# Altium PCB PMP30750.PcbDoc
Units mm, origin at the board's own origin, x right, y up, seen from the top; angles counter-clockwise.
Board outline 55.88 x 60.07 mm, 2 copper layers (Top Layer, Bottom Layer), stack 1.575 mm thick; 36 components, 18 nets, 83 pads, 28 vias.
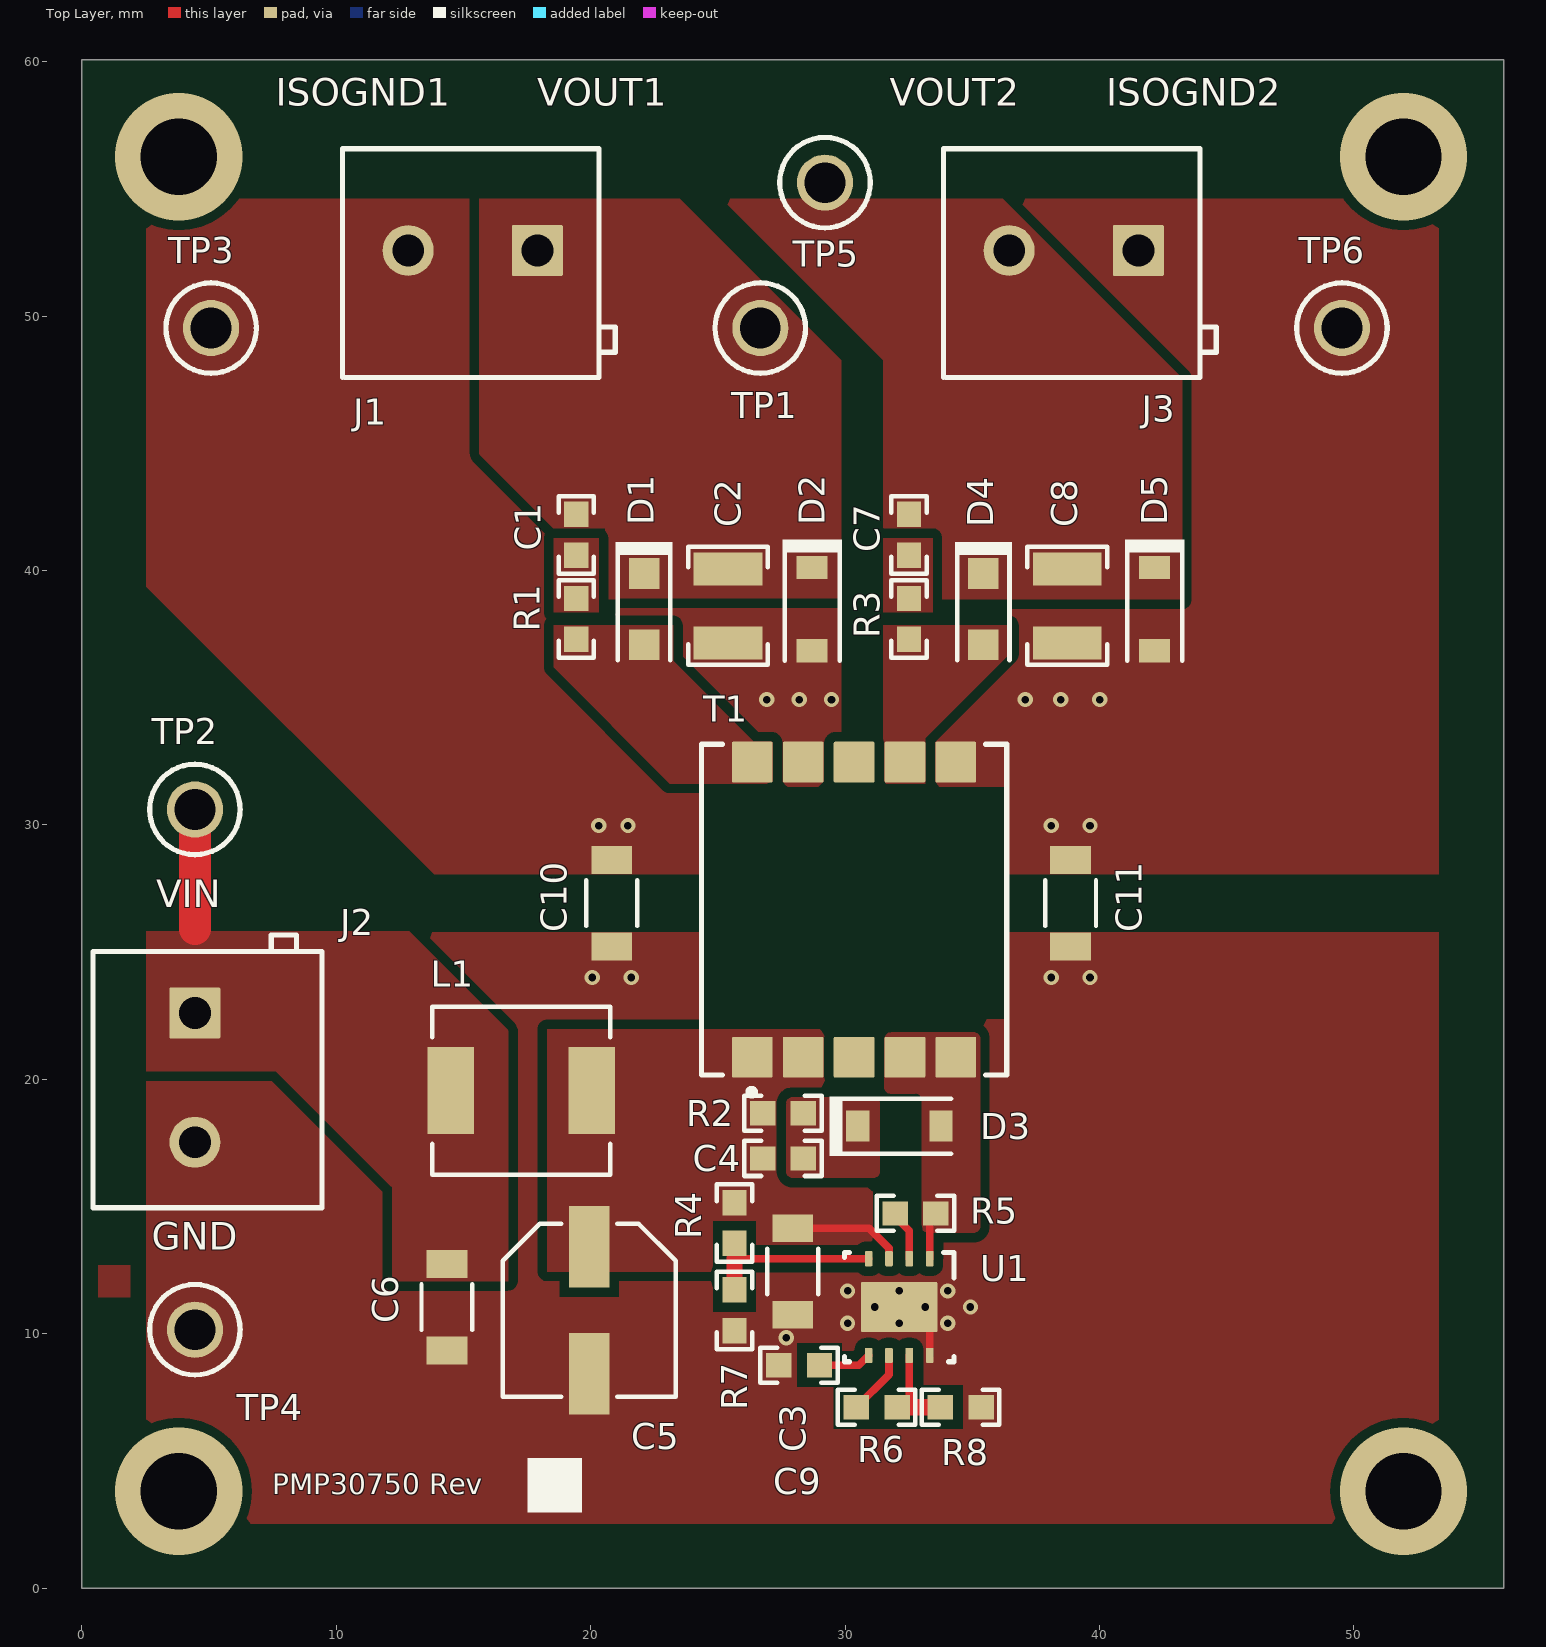
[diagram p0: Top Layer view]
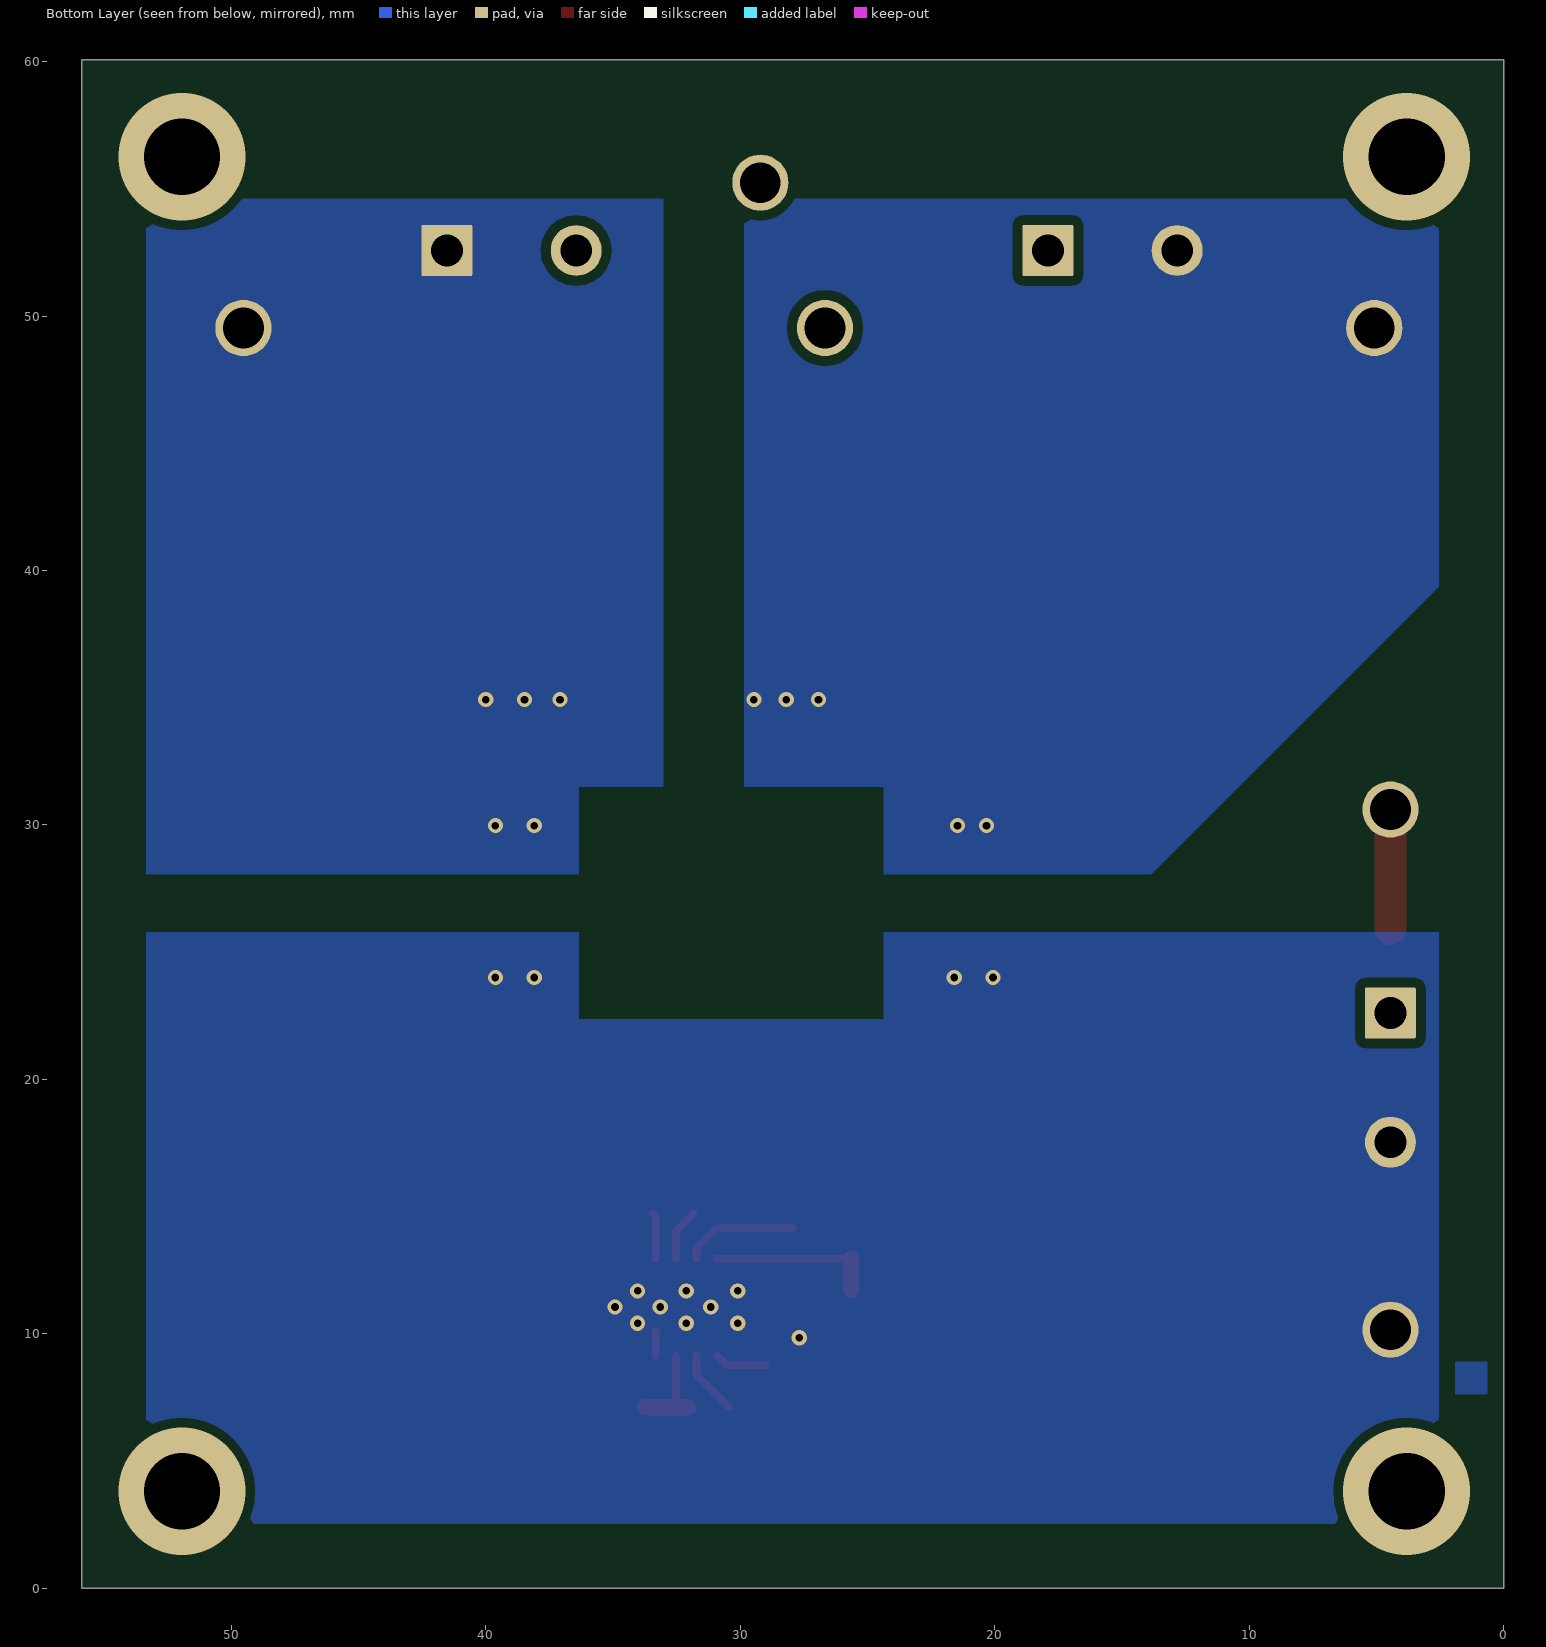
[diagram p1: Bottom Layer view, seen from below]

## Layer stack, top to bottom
Top Solder: solder mask 0.0102, Solder Resist, Dk 3.5
Top Layer: signal copper 0.0356
Dielectric1: core 1.5037, FR-4, Dk 4.8
Bottom Layer: signal copper 0.0356
Bottom Solder: solder mask 0.0102, Solder Resist, Dk 3.5

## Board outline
0,0 55.88,0 55.88,60.071 0,60.071

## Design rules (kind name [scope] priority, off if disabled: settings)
AcuteAngle [All] p1: minimum=4.50000000000000E+0001 checktracksonly=FALSE
AssemblyTestPointUsage [All] p1: valid=2
Clearance Clearance_Keepouts [((IsTrack Or IsArc) And Not InPoly) And IsFree and IsKeepOut vs ((IsTrack Or IsArc) And Not InPoly) And IsFree and IsKeepOut] p1: gap=0 ignorepadtopadclearanceinfootprint=FALSE
Clearance Clearance_BoardEdge_MountingHoles [OnCopper and InComponentClass('Mounting Holes') vs IsKeepOut] p2: gap=1.016 ignorepadtopadclearanceinfootprint=FALSE except(0: Arc-Hole Track-Hole SMDPad-Hole THPad-Hole Via-Hole Fill-Hole Poly-Hole Region-Hole Text-Hole)
Clearance Clearance_BoardEdge_Poly [OnCopper and InPoly vs IsKeepOut] p3: gap=0.635 ignorepadtopadclearanceinfootprint=FALSE except(0: Arc-Hole Track-Hole SMDPad-Hole THPad-Hole Via-Hole Fill-Hole Poly-Hole Region-Hole Text-Hole)
Clearance Clearance_BoardEdge [OnCopper and Not InComponentClass('Logo') and not InComponentClass('FiducialMark') and not InRegion(1000,500,4000,800) and Not IsKeepout vs IsKeepOut] p4: gap=1.905 ignorepadtopadclearanceinfootprint=FALSE except(0: Arc-Hole Track-Hole SMDPad-Hole THPad-Hole Via-Hole Fill-Hole Poly-Hole Region-Hole Text-Hole)
Clearance Clearance_Poly [InPolygon] p5: gap=0.381 ignorepadtopadclearanceinfootprint=FALSE except(0: Arc-Hole Track-Hole SMDPad-Hole THPad-Hole Via-Hole Fill-Hole Poly-Hole Region-Hole Text-Hole)
Clearance [All] p6: gap=0.2 ignorepadtopadclearanceinfootprint=FALSE except(0: Arc-Hole Track-Hole SMDPad-Hole THPad-Hole Via-Hole Fill-Hole Poly-Hole Region-Hole Text-Hole)
ComponentClearance ComponentClearance_MountingHoles_FiducialMarks [InComponentClass('Mounting Holes') vs InComponentClass('FiducialMark')] p1: gap=1.27 collisioncheckmode=3 verticalgap=0.254 showdistances=FALSE
ComponentClearance ComponentClearance_Shunt [InComponentClass('Header') vs InComponentClass('Shunt')] p2: gap=0 collisioncheckmode=3 verticalgap=0 showdistances=FALSE
ComponentClearance ComponentClearance_Logo [InComponentClass('Logo')] p3: gap=1.27 collisioncheckmode=3 verticalgap=0.254 showdistances=FALSE
ComponentClearance ComponentClearance_ScrewToNut [(HasFootprint('NY PMS 440 0025 PH')) vs (HasFootprint('Keystone_1902C'))] p4: gap=0.127 collisioncheckmode=3 verticalgap=0.254 showdistances=FALSE
ComponentClearance ComponentClearance_MountingHoles [InComponentClass('Mounting Holes')] p5: gap=6.35 collisioncheckmode=3 verticalgap=2540 showdistances=FALSE
ComponentClearance ComponentClearance_SmallPassives [HasFootprint('0201*') or HasFootprint('0402*') or HasFootprint('0508') or HasFootprint('0603*') or HasFootprint('0612') or HasFootprint('0805*') or HasFootprint('0815*') or HasFootprint('0830*') or HasFootprint('1206*') or HasFootprint('1210*') or HasFootprint('1808*') or HasFootprint('1812*') or HasFootprint('1825*') or HasFootprint('2010*') or HasFootprint('2220*') or HasFootprint('2225*') or HasFootprint('2512*') or HasFootprint('2728*') or HasFootprint('3518*') vs HasFootprint('0201*') or HasFootprint('0402*') or HasFootprint('0508') or HasFootprint('0603*') or HasFootprint('0612') or HasFootprint('0805*') or HasFootprint('0815*') or HasFootprint('0830*') or HasFootprint('1206*') or HasFootprint('1210*') or HasFootprint('1808*') or HasFootprint('1812*') or HasFootprint('1825*') or HasFootprint('2010*') or HasFootprint('2220*') or HasFootprint('2225*') or HasFootprint('2512*') or HasFootprint('2728*') or HasFootprint('3518*')] p6: gap=0.508 collisioncheckmode=3 verticalgap=0.254 showdistances=FALSE
ComponentClearance ComponentClearance_THtoSMT [IsThruComponent vs IsSMTComponent] p7: gap=2.54 collisioncheckmode=3 verticalgap=0.762 showdistances=FALSE
ComponentClearance ComponentClearance_THtoTH [IsThruComponent vs IsThruComponent] p8: gap=3 collisioncheckmode=3 verticalgap=0.762 showdistances=FALSE
ComponentClearance [All] p9: gap=1.016 collisioncheckmode=3 verticalgap=0.254 showdistances=FALSE
DiffPairsRouting [All] p1: maxlimit=2.54 minlimit=0.254 mostfreqgap=0.254 toplayer_minwidth=0.381 toplayer_maxwidth=0.381 toplayer_prefwidth=0.381 bottomlayer_minwidth=0.381 bottomlayer_maxwidth=0.381 bottomlayer_prefwidth=0.381 maxuncoupledlength=25.4
FabricationTestPointUsage TestPointUsage [All] p1: valid=2 allowmultiple=FALSE
FabricationTestpoint Testpoint [All] p1: side=3 testpointundercomponent=TRUE minsize=1.016 maxsize=2.54 preferedsize=1.524 minholesize=0 maxholesize=1.016 preferedholesize=0.813 testpointgrid=0.025 allowsidetop=TRUE allowsidebottom=TRUE usegrid=TRUE gridtolerance=0
FanoutControl Fanout_LCC [IsLCC] p1: bgadir=Out bgaviamode=Centered fanoutstyle=Auto fanoutdirection=Alternating viagrid=0.025 // Fanout_LCC (Default Rule)
FanoutControl Fanout_BGA [IsBGA] p2: bgadir=Out bgaviamode=Centered fanoutstyle=Auto fanoutdirection=Alternating viagrid=0.025 // Fanout_BGA (Default Rule)
FanoutControl Fanout_Default [All] p4: bgadir=Out bgaviamode=Centered fanoutstyle=Auto fanoutdirection=Alternating viagrid=0.025 // Fanout_Default (Default Rule)
FanoutControl Fanout_Small [(CompPinCount < 5)] p5: bgadir=Out bgaviamode=Centered fanoutstyle=Auto fanoutdirection=OutThenIn viagrid=0.025 // Fanout_Small (Default Rule)
HoleSize [All] p1: absolutevalues=TRUE maxlimit=6.375 minlimit=0.3 maxpercent=80.000 minpercent=20.000
MinimumAnnularRing MinimumAnnularRing_ThermalPadVias [IsVia and InAnyComponent] p1: minimumring=0.15
MinimumAnnularRing [All] p2: minimumring=0.15
MinimumSolderMaskSliver MinimumSolderMaskSliver_Logo [InComponentClass('Logo') vs InComponentClass('Logo')] p1: minsoldermaskwidth=0.018
MinimumSolderMaskSliver [All] p2: minsoldermaskwidth=0.1
PlaneConnect [All] p1: planeconnectstyle=Relief reliefexpansion=0.254 reliefentries=4 reliefconductorwidth=0.254 reliefairgap=0.254
PolygonConnect [All] p1: connectstyle=Direct reliefconductorwidth=0.254 reliefentries=4 polygonreliefangle="90 Angle" airgapwidth=0.254
RoutingVias ThermalPadVias [IsVia and InAnyComponent] p1: holewidth=0.2 width=0.5 viastyle="Through Hole" minholewidth=0.3 minwidth=0.6 maxholewidth=0.33 maxwidth=0.6
RoutingVias [All] p2: holewidth=0.3 width=0.6 viastyle="Through Hole" minholewidth=0.3 minwidth=0.6 maxholewidth=1.016 maxwidth=1.651
SilkToBoardRegionClearance [Not ((IsComment or IsDesignator) And (Hide <> 'False')) and not InRegion(1000,500,4000,800)] p1:
SilkToSilkClearance SilkToSilkClearance_Pb-FreeLogo [(HasFootprint('Pb-Free_Overlay_Medium') OR HasFootprint('Pb-Free_Overlay_Small')) vs (HasFootprint('Pb-Free_Overlay_Medium') OR HasFootprint('Pb-Free_Overlay_Small'))] p1: silktosilkclearance=0
SilkToSilkClearance [All] p2: silktosilkclearance=0.102
SilkToSolderMaskClearance SilkToComonentPadClearance [IsPad and InAnycomponent] p1: minsilkscreentomaskgap=0.127 clearancetoexposedcopper=TRUE
SilkToSolderMaskClearance "Silk to Solder Mask Opening" [All] p2: minsilkscreentomaskgap=0.102 clearancetoexposedcopper=FALSE
SolderMaskExpansion [All] p1: expansion=0.05
Width [All] p1: maxlimit=2.54 minlimit=0.152 preferedwidth=0.254 checkconnectedcopper=TRUE
15 further rules are at their usual default settings.

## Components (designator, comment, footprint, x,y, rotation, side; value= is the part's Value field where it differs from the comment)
C1 "GRM188R71H102KA01D" 0603 19.431,41.402 r270 top value=1000pF
C2 "TMK325B7226MM-PR" 1210_270 25.4,38.608 r270 top value=22uF
C3 "GRM31CR71H475KA12L" 1206_180 27.94,12.446 r270 top value=4.7uF
C4 "GRM188R72A682KA01D" 0603 27.559,16.891 r0 top value=6800pF
C5 "EEE-FK1H100P" SM_RADIAL_D 19.939,10.922 r270 top value=10uF
C6 "GRM31CR71H475KA12L" 1206_180 14.351,11.049 r270 top value=4.7uF
C7 "GRM188R71H102KA01D" 0603 32.512,41.402 r90 top value=1000pF
C8 "TMK325B7226MM-PR" 1210_270 38.735,38.608 r270 top value=22uF
C9 "GRM188R71H223KA01D" 0603 28.194,8.763 r180 top value=0.022uF
C10 "C1206C102KGRACAUTO" 1206_180 20.828,26.924 r270 top value=1000pF
C11 "C1206C102KGRACAUTO" 1206_180 38.862,26.924 r270 top value=1000pF
D1 "PMEG6010CEH,115" SOD-123F 22.098,38.481 r270 top value=60V
D2 "MMSZ5248B-7-F" SOD-123 28.702,38.481 r270 top value=18V
D3 "BAS16D-E3-08" SOD-123 32.131,18.161 r0 top value=100V
D4 "PMEG6010CEH,115" SOD-123F 35.433,38.481 r270 top value=60V
D5 "MMSZ5248B-7-F" SOD-123 42.164,38.481 r270 top value=18V
J1 "ED120/2DS" On-Shore_ED120_2DS 15.367,52.578 r180 top
J2 "ED120/2DS" On-Shore_ED120_2DS 4.445,20.066 r270 top
J3 "ED120/2DS" On-Shore_ED120_2DS 38.989,52.578 r180 top
L1 "IHLP2525CZER100M5A" IHLP-2525CZ 17.272,19.558 r0 top value=10uH
R1 "CRCW060310R0FKEAHP" 0603 19.431,38.1 r90 top value=10.0
R2 "CRCW06036K81FKEA" 0603 27.559,18.669 r180 top value=6.81k
R3 "CRCW060310R0FKEAHP" 0603 32.512,38.1 r90 top value=10.0
R4 "CRCW060349K9FKEA" 0603 25.654,14.351 r90 top value=49.9k
R5 "CRCW0603174KFKEA" 0603 32.766,14.732 r0 top value=174k
R6 "CRCW0603432KFKEA" 0603 31.242,7.112 r180 top value=432k
R7 "CRCW060312K4FKEA" 0603 25.654,10.922 r90 top value=12.4k
R8 "CRCW060312K1FKEA" 0603 34.544,7.112 r180 top value=12.1k
T1 "ZA9704-AL" FP-ZA9704-AL_SMD10-MFG 30.353,26.67 r90 top
TP1 "5010" Keystone5010 26.67,49.53 r0 top
TP2 "5010" Keystone5010 4.445,30.607 r0 top
TP3 "5011" Keystone5011 5.08,49.53 r0 top
TP4 "5011" Keystone5011 4.445,10.16 r0 top
TP5 "5010" Keystone5010 29.21,55.245 r0 top
TP6 "5011" Keystone5011 49.53,49.53 r0 top
U1 "LM5180QNGURQ1" NGU0008C 32.124,11.049 r270 top

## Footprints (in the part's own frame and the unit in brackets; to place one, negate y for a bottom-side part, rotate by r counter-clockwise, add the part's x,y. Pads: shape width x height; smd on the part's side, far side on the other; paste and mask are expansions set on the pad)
0603 [mm] "0603 from SM-752 data"
  rect 1x0.95 smd: 1(-0.8,0) 2(0.8,0)
  silkscreen extent -1.52,-0.69 1.52,0.69, body extent -0.87,-0.47 0.87,0.47, height 1
1206_180 [mm] "1206_180"
  rect 1.1x1.6 smd: 1(-1.7,0) 2(1.7,0)
  silkscreen extent -0.9,-1 0.9,1, body extent -1.75,-0.95 1.75,0.95, height 1.8
1210_270 [mm] "1210"
  rect 1.3x2.7 smd: 1(-1.45,0) 2(1.45,0)
  silkscreen extent -2.32,-1.57 2.32,1.57, body extent -1.7,-1.35 1.7,1.35, height 2.7
FP-ZA9704-AL_SMD10-MFG [mm]
  rrect6% 1.6x1.6 smd paste+0 mask+0: 1(-5.8,4) 2(-5.8,2) 3(-5.8,0) 4(-5.8,-2) 5(-5.8,-4) 6(5.8,-4) 7(5.8,-2) 8(5.8,0) 9(5.8,2) 10(5.8,4)
  silkscreen extent -7.3,-6 6.5,6, body extent -6.7,-6.1 6.7,6.1, height 0.25
IHLP-2525CZ [mm] "Vishay Dale recommended land pattern.  Document 34190 rev 10-Aug-06"
  rect 1.83x3.43 smd: 1(-2.77,0) 2(2.77,0)
  silkscreen extent -3.5,-3.3 3.5,3.3, body extent -3.62,-3.36 3.62,3.36, height 3
Keystone5010 [mil] "Keystone Multipurpose loops"
  round 87 hole 63: 1(0,0)
  silkscreen extent -70,-70 70,70, body extent -63,-63 63,62, height 319
Keystone5011 [mil] "Keystone Multipurpose loops"
  round 87 hole 63: 1(0,0)
  silkscreen extent -70,-70 70,70, body extent -63,-63 63,62, height 319
NGU0008C [mm] "SON, 8-Leads, Body 4x4mm, Pitch 0.8mm"
  rrect33% 0.6x0.3 smd: 1(-1.9,1.2) 2(-1.9,0.4) 3(-1.9,-0.4) 4(-1.9,-1.2) 5(1.9,-1.2) 6(1.9,-0.4) 7(1.9,0.4) 8(1.9,1.2)
  rrect8% 1.75x1.31 on Top Paste: 9(0,0.755) 9(0,-0.755)
  rrect5% 1.98x3 smd paste-1.5: 9(0,0)
  silkscreen extent -2.15,-2.15 2.15,2.15, body extent -2,-2 2,2, height 0.77
On-Shore_ED120_2DS [mm] "ONSHORE"
  rrect5% 2x2 hole 1.25: 1(-2.54,0)
  round 2 hole 1.25: 2(2.54,0)
  silkscreen extent -5.6,-4 5.12,5, body extent -5.78,-4 5.08,5, height 13
SM_RADIAL_D [mm] "6.3 x 5.8mm:  Panasonic D"
  rect 3.2x1.6 smd: 1(-2.5,0) 2(2.5,0)
  silkscreen extent -3.4,-3.4 3.4,3.4, body extent -3.4,-3.4 3.4,3.4, height 6.1
SOD-123 [mm] "On Semi recommended land pattern"
  rect 0.915x1.22 smd: 1(-1.637,0) 2(1.637,0)
  silkscreen extent -2.74,-1.17 2.03,1.17, body extent -1.93,-0.9 1.93,0.9, height 1.35
SOD-123F [mm] "NXP recommended land pattern"
  rect 1.2x1.2 smd paste-0.05: 1(-1.4,0) 2(1.4,0)
  silkscreen extent -2.64,-1.12 2.01,1.12, body extent -1.8,-0.85 1.8,0.85, height 1.2

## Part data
C1 C7: library part CMP-0007432-5, "CAP, CERM, 1000 pF, 50 V, +/- 10%, X7R, 0603", Cap_Case=0603, Manufacturer=MuRata, Supplier Part Number 1=490-1494-1-ND, TempCo=X7R, Tolerance_%=10%, Value1=Unknown, Value2=50V, ValueDisplayed=1000pF
C2 C8: library part CMP-0009255-2, "CAP, CERM, 22 uF, 25 V, +/- 10%, X7R, AEC-Q200 Grade 1, 1210", Cap_Case=1210, Manufacturer="Taiyo Yuden", TempCo=X7R, Tolerance_%=10%, Value1=Unknown, Value2=25V, ValueDisplayed=22uF
C3 C6: library part CMP-0008969-2, "CAP, CERM, 4.7 uF, 50 V, +/- 10%, X7R, 1206", Cap_Case=2220, Manufacturer=MuRata, Supplier Part Number 1=24R6347, TempCo=X7R, Tolerance_%=10%, Value1=Unknown, Value2=50V, ValueDisplayed=4.7uF
C4: library part CMP-0007487-4, "CAP, CERM, 6800 pF, 100 V, +/- 10%, X7R, 0603", Cap_Case=0603, Manufacturer=MuRata, Supplier Part Number 1=GRM188R72A682KA01D-ND, TempCo=X7R, Tolerance_%=10%, Value1=Unknown, Value2=100V, ValueDisplayed=6800pF
C5: library part CMP-0011175-2, "CAP, AL, 10 uF, 50 V, +/- 20%, 0.88 ohm, AEC-Q200 Grade 2, SMD", Cap_Case=D, Manufacturer=Panasonic, Supplier Part Number 1=PCE3807CT-ND, Tolerance_%=20%, Value1="0.88 ohm", Value2=50V, ValueDisplayed=10uF
C9: library part CMP-0007444-4, "CAP, CERM, 0.022 uF, 50 V, +/- 10%, X7R, 0603", Cap_Case=0603, Manufacturer=MuRata, Supplier Part Number 1=490-1517-1-ND, TempCo=X7R, Tolerance_%=10%, Value1=Unknown, Value2=50V, ValueDisplayed=0.022uF
C10 C11: library part CMP-0008579-2, "CAP, CERM, 1000 pF, 2000 V, +/- 10%, X7R, AEC-Q200 Grade 1, 1206", Cap_Case=1206, Manufacturer=Kemet, Supplier Part Number 1=399-12976-1-ND, TempCo=X7R, Tolerance_%=10%, Value1=Unknown, Value2=2000V, ValueDisplayed=1000pF
D1 D4: library part CMP-0028377-2, "Diode, Schottky, 60 V, 1 A, SOD-123F", Manufacturer=Nexperia, Value1=1A, Value2=0.57V
D2 D5: library part CMP-0005755-1, "Diode, Zener, 18 V, 500 mW, SOD-123", Manufacturer="Diodes Inc.", Power_W=500mW, Supplier Part Number 1=MMSZ5248B-FDICT-ND, Value1=0.5W
D3: library part CMP-0080761-1, "Diode, Switching, 100 V, 0.25 A, AEC-Q101, SOD-123", Manufacturer=Vishay-Semiconductor, Supplier Part Number 1=BAS16D-E3-08GICT-ND, Value1=0.25A, Value2=1.25V
J1 J2 J3: library part CMP-0074910-1, "Terminal Block, 5.08 mm, 2x1, Brass, TH", Color=Blue, Current_A=15A, Manufacturer="On-Shore Technology", Supplier Part Number 1=ED1609-ND, Voltage_V=300V
L1: library part CMP-0063375-1, "Inductor, Shielded, 10 uH, 2.9 A, 0.0719 ohm, SMD", Manufacturer=Vishay-Dale, Supplier Part Number 1=IHLP2525CZER100M5A-ND, Value1="0.0719 ohm", Value2=2.9A, ValueDisplayed=10uH
R1 R3: library part CMP-0022004-4, "RES, 10.0, 1%, 0.25 W, AEC-Q200 Grade 0, 0603", Manufacturer=Vishay-Dale, Power_W=250mW, Supplier Part Number 1=541-10.0SCT-ND, TempCo="100 ppm/C", Tolerance_%=1%, Value2=0.25W, Value_Code=10R0, ValueDisplayed=10.0
R2: library part CMP-0022563-4, "RES, 6.81 k, 1%, 0.1 W, AEC-Q200 Grade 0, 0603", Manufacturer=Vishay-Dale, Power_W=100mW, Supplier Part Number 1=541-6.81KHCT-ND, TempCo="100 ppm/C", Tolerance_%=1%, Value2=0.1W, Value_Code=6k81, ValueDisplayed=6.81k
R4: library part CMP-0022447-4, "RES, 49.9 k, 1%, 0.1 W, AEC-Q200 Grade 0, 0603", Manufacturer=Vishay-Dale, Power_W=100mW, Supplier Part Number 1=541-49.9KHCT-ND, TempCo="100 ppm/C", Tolerance_%=1%, Value2=0.1W, Value_Code=49k9, ValueDisplayed=49.9k
R5: library part CMP-0022085-4, "RES, 174 k, 1%, 0.1 W, AEC-Q200 Grade 0, 0603", Manufacturer=Vishay-Dale, Power_W=100mW, Supplier Part Number 1=541-174KHCT-ND, TempCo="100 ppm/C", Tolerance_%=1%, Value2=0.1W, Value_Code=174k
R6: library part CMP-0022420-4, "RES, 432 k, 1%, 0.1 W, AEC-Q200 Grade 0, 0603", Manufacturer=Vishay-Dale, Power_W=100mW, Supplier Part Number 1=541-432KHCT-ND, TempCo="100 ppm/C", Tolerance_%=1%, Value2=0.1W, Value_Code=432k, ValueDisplayed=DNP
R7: library part CMP-0022031-4, "RES, 12.4 k, 1%, 0.1 W, AEC-Q200 Grade 0, 0603", Manufacturer=Vishay-Dale, Power_W=100mW, Supplier Part Number 1=541-12.4KHCT-ND, TempCo="100 ppm/C", Tolerance_%=1%, Value2=0.1W, Value_Code=12k4, ValueDisplayed=12.4k
R8: library part CMP-0022030-4, "RES, 12.1 k, 1%, 0.1 W, AEC-Q200 Grade 0, 0603", Manufacturer=Vishay-Dale, Power_W=100mW, Supplier Part Number 1=541-12.1KHCT-ND, TempCo="100 ppm/C", Tolerance_%=1%, Value2=0.1W, Value_Code=12k1, ValueDisplayed=12.1k
T1: library part CMP-0086949-1, "FLYBACK TRANSFORMER", Manufacturer=Coilcraft
TP1 TP2 TP5: library part CMP-0055147-1, "Test Point, Multipurpose, Red, TH", Color=Red, Manufacturer=Keystone, Supplier Part Number 1=36-5010-ND
TP3 TP4 TP6: library part CMP-0055148-1, "Test Point, Multipurpose, Black, TH", Color=Black, Manufacturer=Keystone, Supplier Part Number 1=36-5011-ND
U1: library part CMP-0078633-2, "70-V PSR Flyback Converter With 100-V, 1.2-A Power Switch and Ultra-Low IQ, NGU0008C (WSON-8)", Alternate Manufacturer="Texas Instruments", Alternate PartNumber=LM5180QNGUTQ1

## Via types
v1: diameter 0.6, hole 0.3, Top Layer to Bottom Layer, tented both sides, 20 vias
v2: diameter 0.6, hole 0.3, Top Layer to Bottom Layer, 4 vias
v3: diameter 5, hole 3, Top Layer to Bottom Layer, 4 vias

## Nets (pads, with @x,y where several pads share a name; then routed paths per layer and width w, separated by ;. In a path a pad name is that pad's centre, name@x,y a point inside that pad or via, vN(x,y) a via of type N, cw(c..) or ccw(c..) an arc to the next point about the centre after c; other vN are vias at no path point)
GND: C3.2 C5.2 C6.2 C9.2 C10.2 C11.2 J2.2 R7.1 R8.1 TP4.1 U1.8 U1.9@32.124,11.049 | length 1
  Top Layer w0.305: U1.8 U1.9@33.324,10.122
  other v1: 27.686,9.838 30.099,10.414 34.036,10.414 34.925,11.049 30.099,11.684 34.036,11.684 20.066,24.003 21.59,24.003 38.1,24.003 39.624,24.003
  other v2: 32.124,10.414 31.166,11.049 33.147,11.049 32.124,11.684
ISOGND1: C2.2 C10.1 D2.2 J1.2 T1.9 TP3.1
  other v1: 20.32,29.972 21.463,29.972 26.924,34.925 28.194,34.925 29.464,34.925
ISOGND2: C8.2 C11.1 D5.2 J3.1 T1.6 TP6.1
  other v1: 38.1,29.972 39.624,29.972 37.084,34.925 38.481,34.925 40.005,34.925
NetC1_2: C1.2 R1.2
NetC3_1: C3.1 C4.1 C5.1 L1.2 R2.2 R4.2 T1.1 T1.2 U1.3 | length 4.5
  Top Layer w0.305: C3.1 30.939,14.146 31.724,13.361 U1.3
NetC4_2: C4.2 D3.1 R2.1
NetC6_1: C6.1 J2.1 L1.1 TP2.1 | length 4.7
  Top Layer w1.27: 4.445,25.908 TP2.1
NetC7_1: C7.1 R3.2
NetC9_1: C9.1 U1.5 | length 2.1
  Top Layer w0.305: C9.1 30.538,8.763 U1.5
NetD1_2: D1.2 R1.1 T1.10
NetD3_2: D3.2 R5.2 T1.4 T1.5 U1.1 | length 1.8
  Top Layer w0.305: U1.1 33.324,14.617 R5.2@33.439,14.732
NetD4_2: D4.2 R3.1 T1.7
NetR4_1: R4.1 R7.2 U1.4 | length 6.5
  Top Layer w0.305: 25.654,12.954 25.659,12.949 U1.4
  Top Layer w0.635: R7.2 25.654,12.954
NetR5_1: R5.1 U1.2 | length 2.1
  Top Layer w0.305: R5.1@31.839,14.732 32.524,14.047 U1.2
NetR6_1: R6.1 R8.2 U1.7 | length 3.6
  Top Layer w0.305: R6.1@32.524,7.239 U1.7
  Top Layer w0.635: R6.1 R8.2
NetR6_2: R6.2 U1.6 | length 2.6
  Top Layer w0.305: R6.2 31.724,8.394 U1.6
VOUT1: C1.1 C2.1 D1.1 D2.1 J1.1 TP1.1
VOUT2: C7.2 C8.1 D4.1 D5.1 J3.2 TP5.1
pads on no net: T1.3 T1.8 U1.9@31.369,11.049 U1.9@32.879,11.049
copper on no net:
  other v3: 3.81,3.81 51.946,3.81 3.81,56.26 51.946,56.26

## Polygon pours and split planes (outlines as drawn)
ISOGND1 on Bottom Layer "ISOGND1_L02_P134" (solid, remove dead copper, pour order 134): 29.845,28.067 13.843,28.067 2.54,39.37 2.54,54.61 29.845,54.61
ISOGND2 on Bottom Layer "ISOGND2_L02_P130" (solid, remove dead copper, pour order 130): 53.34,28.067 53.34,54.61 33.02,54.61 33.02,28.067
GND on Bottom Layer "GND_L02_P122" (solid, remove dead copper, pour order 122): 2.54,25.781 53.34,25.781 53.34,2.54 2.54,2.54
no net on Bottom Layer "NONET_L02_P072" (solid, pour order 72): 0.635,7.62 0.635,8.89 1.905,8.89 1.905,7.62
ISOGND1 on Top Layer "ISOGND1_L01_P132" (solid, remove dead copper, pour order 132): 29.845,28.067 13.843,28.067 2.54,39.37 2.54,54.61 29.845,54.61
ISOGND2 on Top Layer "ISOGND2_L01_P128" (solid, remove dead copper, pour order 128): 53.34,28.067 53.34,54.61 31.515,54.61 31.515,28.067
VOUT2 on Top Layer "VOUT2_L01_P126" (solid, remove dead copper, pour order 126): 43.243,38.862 43.243,47.561 36.195,54.61 26.67,54.61 25.146,54.61 31.496,48.26 31.496,38.862
VOUT1 on Top Layer "VOUT1_L01_P124" (solid, remove dead copper, pour order 124): 29.845,38.862 29.845,48.26 23.495,54.61 15.621,54.61 15.621,44.577 18.542,41.656 20.574,41.656 20.574,38.862
GND on Top Layer "GND_L01_P120" (solid, remove dead copper, pour order 120): 2.54,25.781 53.34,25.781 53.34,2.54 2.54,2.54
NetC6_1 on Top Layer "NETC6_1_L01_P118" (solid, remove dead copper, pour order 118): 16.764,21.918 12.864,25.818 2.54,25.818 2.54,20.32 7.62,20.32 12.192,15.748 12.192,12.065 16.764,12.065
NetD3_2 on Top Layer "NETD3_2_L01_P116" (solid, pour order 116): 31.542,21.59 cw(c31.837,21.55) 31.877,21.844 35.052,21.844 cw(c35.052,21.59) 35.306,21.59 35.306,14.224 cw(c35.052,14.224) 35.052,13.97 33.274,13.97 cw(c33.274,14.224) 33.02,14.224 33.02,19.174 ccw(c32.763,19.174) 32.763,19.431 31.839,19.431 cw(c31.818,19.706) 31.542,19.685
NetC7_1 on Top Layer "NETC7_1_L01_P114" (solid, remove dead copper, pour order 114): 31.496,41.275 31.509,41.262 31.509,38.354 33.439,38.354 33.439,41.275
NetC1_2 on Top Layer "NETC1_2_L01_P112" (solid, remove dead copper, pour order 112): 18.542,38.354 18.542,41.275 20.32,41.275 20.32,38.354
NetD1_2 on Top Layer "NETD1_2_L01_P110" (solid, remove dead copper, pour order 110): 27.178,33.274 26.416,33.274 23.241,36.449 23.241,37.846 18.542,37.846 18.542,36.195 23.114,31.623 27.178,31.623
NetD4_2 on Top Layer "NETD4_2_L01_P108" (solid, remove dead copper, pour order 108): 31.496,31.623 31.496,37.846 36.449,37.846 36.449,36.703 33.147,33.401 33.147,31.623
NetC3_1 on Top Layer "NETC3_1_L01_P106" (solid, remove dead copper, pour order 106): 31.877,12.446 18.288,12.446 18.288,21.971 31.877,21.971
NetC4_2 on Top Layer "NETC4_2_L01_P104" (solid, remove dead copper, pour order 104): 31.369,19.05 ccw(c31.115,19.05) 31.115,19.304 27.94,19.304 ccw(c27.94,19.05) 27.686,19.05 27.686,16.383 ccw(c27.94,16.383) 27.94,16.129 31.115,16.129 ccw(c31.115,16.383) 31.369,16.383
no net on Top Layer "NONET_L01_P100" (solid, remove dead copper, pour order 100): 27.559,19.394
no net on Top Layer "NONET_L01_P078" (solid, pour order 78): 0.635,11.43 0.635,12.7 1.905,12.7 1.905,11.43
no net on Top Overlay "NONET_L-01_P-001" (solid): 17.526,2.984 17.526,5.112 19.653,5.112 19.653,2.984

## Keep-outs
Keep-Out Layer:
  text ".Layer_Name" at 14.656,-21.806 h1.52

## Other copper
Top Layer:
  pour cut-out: 24.353,31.496 24.353,22.352 36.353,22.352 36.353,31.496
  text ".Layer_Name" at 14.656,-21.806 h1.52
Bottom Layer:
  pour cut-out: 24.353,31.496 24.353,22.352 36.353,22.352 36.353,31.496
  text ".Layer_Name" at 14.656,-21.806 h1.52

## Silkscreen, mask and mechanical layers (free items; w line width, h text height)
Top Overlay:
  text "ISOGND1" at 7.62,57.912 h1.85
  text "VOUT1" at 17.907,57.912 h1.85
  text "VOUT2" at 31.75,57.912 h1.85
  text "ISOGND2" at 40.259,57.912 h1.85
  text "VIN" at 2.921,26.416 h1.85
  text "GND" at 2.743,12.954 h1.85
  text "PMP30750 Rev" at 7.493,3.683 h0.8
  text ".Layer_Name" at 14.656,-21.806 h1.52
Bottom Overlay:
  text ".Layer_Name" at 14.656,-21.806 h1.52
Top Paste:
  text ".Layer_Name" at 14.656,-21.806 h1.52
Bottom Paste:
  text ".Layer_Name" at 14.656,-21.806 h1.52
Top Solder:
  text ".Layer_Name" at 14.656,-21.806 h1.52
  text ".Layer_Name" at 14.656,-21.806 h1.52
Bottom Solder:
  text ".Layer_Name" at 14.656,-21.806 h1.52
Drill Guide:
  text ".Layer_Name" at 14.656,-21.806 h1.52
M1 Board Outline:
  lines w0.3: 132.207,0 132.334,0.127 ; 0,0 0,60.071 55.88,60.071 55.88,0 0,0
  text ".Layer_Name" at 14.656,-21.806 h1.52
M2 Board Dimensions:
  rectangle: 3.175,-10.16 12.7,-6.985
  rectangle: 0,-6.985 3.175,-3.81
  lines w0.178: 0,-6.985 25.4,-6.985 ; 3.175,-10.16 3.175,-3.81 ; 6.35,-10.16 6.35,-3.81 ; 12.7,-10.16 12.7,-3.81 ; 19.05,-10.16 19.05,-3.81 ; 0,-10.16 0,-3.81 25.4,-3.81 25.4,-10.16 0,-10.16
  text "PMP30578" at 0,61.214 h1.85
  text ".Layer_Name" at 14.656,-21.806 h1.52
M3 3D STEP Top:
  text ".Layer_Name" at 14.656,-21.806 h1.52
M4 3D STEP Bottom:
  text ".Layer_Name" at 14.656,-21.806 h1.52
M5 Assembly Top:
  lines w0.254: -7.417,-23.626 160.223,-23.626 ; -7.417,-18.462 160.274,-18.462 ; -7.417,-13.297 -7.417,-28.791 94.31,-28.791 160.274,-28.791 160.274,-13.297 -7.404,-13.297 -7.404,-28.791 32.614,-28.791 ; 55.194,-28.791 55.194,-13.297 ; 87.376,-18.462 87.376,-13.297 ; 108.712,-18.462 108.712,-13.297 ; 124.511,-28.956 124.511,-23.804
  text "COMPONENTS MARKED 'DNP' SHOULD NOT BE POPULATED." at 29.299,-8.09 h1.52
  text "ASSEMBLY VARIANT:" at 29.286,-11.024 h1.52
  text ".VariantName" at 55.601,-11.024 h1.52
  text "PCB VIEWED FROM TOP SIDE" at -5.804,-16.654 h1.52
  text "BOARD #:" at 57.099,-16.654 h1.52
  text ".PRJ_Number" at 70.955,-16.654 h1.52
  text "REV:" at 92.405,-16.654 h1.52
  text ".PCB_Rev" at 99.809,-16.654 h1.52
  text "SVN REV:" at 113.69,-16.654 h1.52
  text ".VersionControl_RevNumber" at 126.543,-16.654 h1.52
  text "TID #:" at 57.099,-21.819 h1.52
  text ".TID" at 70.955,-21.819 h1.52
  text "PLOT NAME =" at -5.804,-27.034 h1.52
  text ".plot_File_Name" at 14.656,-27.034 h1.52
  text "GENERATED    :" at 57.15,-27.034 h1.52
  text ".Print_Date" at 79.235,-27.034 h1.52
  text ".Print_Time" at 97.752,-27.034 h1.52
  text "TEXAS INSTRUMENTS" at 129.87,-27.034 h1.52
M6 Assembly Bottom:
  lines w0.254: -7.429,-18.474 160.261,-18.474 ; -7.379,-23.639 160.261,-23.639 ; 28.334,-28.969 28.334,-23.817 ; 44.133,-18.474 44.133,-13.31 ; 65.468,-18.474 65.468,-13.31 ; 97.65,-28.804 97.65,-13.31 ; 120.231,-28.804 160.249,-28.804 160.249,-13.31 -7.429,-13.31 -7.429,-28.804 58.534,-28.804 160.261,-28.804 160.261,-13.31
  text "COMPONENTS MARKED 'DNP' SHOULD NOT BE POPULATED." at 154.991,-8.077 h1.52
  text ".VariantName" at 128.473,-11.024 h1.52
  text "ASSEMBLY VARIANT:" at 154.864,-11.024 h1.52
  text ".VersionControl_RevNumber" at 26.302,-16.667 h1.52
  text "SVN REV:" at 39.154,-16.667 h1.52
  text ".PCB_Rev" at 53.035,-16.667 h1.52
  text "REV:" at 60.439,-16.667 h1.52
  text ".PRJ_Number" at 81.89,-16.667 h1.52
  text "BOARD #:" at 95.745,-16.667 h1.52
  text "PCB VIEWED FROM BOTTOM SIDE" at 158.648,-16.667 h1.52
  text ".TID" at 81.89,-21.831 h1.52
  text "TID #:" at 95.745,-21.831 h1.52
  text "TEXAS INSTRUMENTS" at 22.974,-27.047 h1.52
  text ".Print_Time" at 55.093,-27.047 h1.52
  text ".Print_Date" at 73.609,-27.047 h1.52
  text "GENERATED    :" at 95.694,-27.047 h1.52
  text ".plot_File_Name" at 138.189,-27.047 h1.52
  text "PLOT NAME =" at 158.648,-27.047 h1.52
M9 Title Sheet:
  drawing of 57 lines, arcs and shapes, not listed
  text "1" at 18.792,204.127 h1.78
  text "2" at 82.182,204.127 h1.78
  text "3" at 145.411,204.127 h1.78
  text "4" at 209.08,204.127 h1.78
  text "5" at 272.555,204.127 h1.78
  text "6" at 336.182,204.127 h1.78
  text "A" at -10.579,175.095 h1.78
  text "A" at 365.341,175.095 h1.78
  text "B" at -10.579,114.643 h1.78
  text "B" at 365.341,114.643 h1.78
  text "C" at -10.579,54.318 h1.78
  text "C" at 365.341,54.318 h1.78
  text "PROJECT TITLE:" at 288.125,7.048 h1.14
  text ".PRJ_Title" at 289.395,3.662 h1.78
  text "DESIGNED FOR:" at 288.125,-0.597 h1.14
  text ".PRJ_Customer" at 289.395,-4.153 h1.78
  text "D" at -10.579,-5.88 h1.78
  text "D" at 365.341,-5.88 h1.78
  text "FILE NAME:" at 288.125,-8.217 h1.14
  text ".PCB_File_Name_No_Path" at 289.395,-11.265 h1.78
  text "Texas Instruments (TI) and/or its licensors do not warrant the accuracy or completeness of this specification" at 161.9,-15.376 h1.14
  text "ENGINEER:" at 288.125,-15.583 h1.14
  text "LAYOUT BY:" at 326.352,-15.583 h1.14
  text "or any information contained therein. TI and/or its licensors do not warrant that this design will meet" at 160.757,-18.237 h1.14
  text ".PRJ_Engineer" at 289.395,-19.52 h1.78
  text ".PCB_Layout" at 327.635,-19.52 h1.78
  text "the specifications, will be suitable for your application or fit for any particular purpose, or will operate in" at 160.757,-21.099 h1.14
  text ".Layer_Name" at 14.656,-21.806 h1.52
  text "ALTIUM DESIGNER VERSION:" at 326.352,-23.457 h1.14
  text "an implementation. TI and/or its licensors do not warrant that the design is production worthy. You should" at 160.757,-23.961 h1.14
  text "completely validate and test your design implementation to confirm the system functionality for your application." at 161.9,-26.822 h1.14
  text ".print_Scale" at 289.395,-26.843 h1.78
  text ".Application_BuildNumber" at 327.635,-26.843 h1.78
  text "1" at 18.792,-32.093 h1.78
  text "2" at 82.182,-32.093 h1.78
  text "3" at 145.411,-32.093 h1.78
  text "4" at 209.08,-32.093 h1.78
  text "5" at 272.555,-32.093 h1.78
  text "6" at 336.182,-32.093 h1.78
M10 Fab Notes:
  drawing of 173 lines, arcs and shapes, not listed
  text "DESIGN INFORMATION" at 314.376,157.505 h1.52
  text "MIN. TRACK WIDTH:" at 298.004,152.933 h1.52
  text "8" at 325.849,152.933 h1.52
  text "MIL" at 329.78,152.933 h1.52
  text "MIN. CLEARANCE:" at 298.004,149.581 h1.52
  text "0.2" at 324.325,149.581 h1.52
  text "mm" at 329.78,149.581 h1.52
  text "MIN. VIA PAD SIZE:" at 298.004,146.228 h1.52
  text "24" at 325.087,146.228 h1.52
  text "MIL" at 329.78,146.228 h1.52
  text "0.05mm (2MIL)" at 315.657,142.628 h1.52
  text "MINIMUM ANNULAR RING" at 289.642,142.52 h1.52
  text "EXTERNAL" at 333.641,142.52 h1.52
  text "PER" at 294.722,139.522 h1.52
  text "IPC-D-275 CLASS 2 LEVEL C" at 300.31,139.522 h1.52
  text "MIL, HOLES" at 338.111,136.67 h1.52
  text "+/-" at 328.143,136.652 h1.52
  text "+/-" at 349.834,136.652 h1.52
  text "REGISTRATION TOLERANCES:" at 289.642,136.525 h1.52
  text "METAL" at 320.116,136.525 h1.52
  text "5" at 334.752,136.525 h1.52
  text "3" at 355.91,136.525 h1.52
  text "MIL" at 358.863,136.525 h1.52
  text "+/-" at 349.834,133.655 h1.52
  text "HOLE SIZE TOLERANCE (UNLESS OTHERWISE SPECIFIED):" at 289.642,133.528 h1.52
  text "3" at 355.91,133.528 h1.52
  text "MIL" at 358.863,133.528 h1.52
  text "MATERIAL:" at 287.743,128.208 h1.52
  text "FR-4 High Tg" at 312.799,124.643 h1.52
  text "FR-408" at 298.436,124.425 h1.52
  text "OTHER" at 336.231,124.425 h1.52
  text "X" at 308.864,124.333 h1.52
  text "62 MIL (1.6mm) +/-10%" at 306.567,120.292 h1.52
  text "THICKNESS:" at 289.642,120.184 h1.52
  text "X" at 303.311,120.184 h1.52
  text "OTHER" at 339.203,120.184 h1.52
  text "TOLERANCE:" at 289.642,116.17 h1.52
  text "X" at 310.96,116.17 h1.52
  text "ANSI IPC-6012 TYPE 3 CLASS 2" at 315.709,116.17 h1.52
  text "OTHER +/-" at 315.708,112.208 h1.52
  text "BOW & TWIST:" at 289.642,108.22 h1.52
  text "X" at 310.96,108.22 h1.52
  text "ANSI IPC-6012 TYPE 3 CLASS 2" at 315.709,108.22 h1.52
  text "OTHER +/-" at 315.708,104.194 h1.52
  text "DRILLING:" at 287.743,100.676 h1.52
  text "REFERENCE:" at 289.642,97.705 h1.52
  text "X" at 306.107,97.705 h1.52
  text "AS SHOWN" at 310.857,97.705 h1.52
  text "X" at 328.992,97.705 h1.52
  text "NC_DRILL FILES" at 332.472,97.705 h1.52
  text "PTH COPPER THICKNESS:" at 289.642,93.691 h1.52
  text "X" at 318.35,93.691 h1.52
  text "20-30 um" at 321.83,93.691 h1.52
  text "OTHER" at 340.041,93.691 h1.52
  text "BOARD FINISH:" at 287.743,89.653 h1.52
  text "SILKSCREEN:" at 291.685,86.656 h1.52
  text "X" at 315.784,86.656 h1.52
  text "TOP" at 318.985,86.656 h1.52
  text "X" at 328.738,86.656 h1.52
  text "BOTTOM" at 331.964,86.656 h1.52
  text "SILKSCREEN COLOR:" at 291.685,82.414 h1.52
  text "X" at 315.758,82.414 h1.52
  text "WHITE" at 318.985,82.414 h1.52
  text "OTHER" at 331.964,82.414 h1.52
  text "X" at 319.086,78.37 h1.52
  text "GREEN" at 322.312,78.37 h1.52
  text "OTHER" at 338.009,78.37 h1.52
  text "SOLDER RESIST COLOR:" at 291.685,78.096 h1.52
  text "X" at 319.086,74.052 h1.52
  text "MATTE" at 322.312,74.052 h1.52
  text "SEMI-GLOSS" at 337.998,74.036 h1.52
  text "IMMERSION GOLD (ENIG)" at 314.692,69.264 h1.52
  text "ENEPIG" at 348.666,69.18 h1.52
  text "SURFACE FINISH:" at 287.743,69.155 h1.52
  text "X" at 309.944,69.155 h1.52
  text "IMM. TIN/SILVER OR EQUIV" at 296.113,65.167 h1.52
  text "OTHER" at 332.472,65.167 h1.52
  text "ARRAY/PANEL:" at 287.743,60.621 h1.52
  text "CUT AND TRIM PER M1 BOARD OUTLINE" at 314.692,60.512 h1.52
  text "N.C. ROUTE" at 314.692,56.658 h1.52
  text "X" at 331.939,56.658 h1.52
  text "V. SCORE" at 336.689,56.658 h1.52
  text "CERTIFICATION:" at 287.743,53.178 h1.52
  text "MATERIALS AND WORKMANSHIP FOR ALL PCBS" at 306.158,53.178 h1.52
  text "TO MEET OR EXCEED THE REQUIREMENTS OF:" at 306.158,50.689 h1.52
  text "X" at 296.671,47.222 h1.52
  text "ANSI IPC-A-600F CLASS ->" at 300.202,47.222 h1.52
  text "X" at 341.834,47.222 h1.52
  text "2" at 344.855,47.222 h1.52
  text "1" at 336.854,47.184 h1.52
  text "3" at 353.846,47.184 h1.52
  text "X" at 317.348,43.171 h1.52
  text "RoHS" at 320.826,43.171 h1.52
  text "OTHER" at 337.194,43.171 h1.52
  text "PER ORDER" at 347.28,43.171 h1.52
  text "ALL BOARDS MUST MEET OR EXCEED UL94-V0 REQUIREMENTS." at 288.442,38.964 h1.52
  text "PCB MUST BEAR THE UL94V-0 UL REGISTERED MATERIAL ID NUMBER" at 288.442,35.916 h1.52
  text "ADDITIONAL REQUIREMENTS:" at 287.743,31.512 h1.52
  text "MICROSECTION:" at 289.642,28.591 h1.52
  text "YES" at 312.648,28.591 h1.52
  text "REQUIRED" at 334.53,24.625 h1.52
  text "BARE BOARD ELEC. TEST:" at 289.642,24.553 h1.52
  text "NONE" at 322.808,24.553 h1.52
  text "X" at 331.304,24.553 h1.52
  text "PER ORDER" at 349.566,24.553 h1.52
  text ".Layer_Name" at 14.656,-21.806 h1.52
M11 Gerber Information:
  lines w0.254: -7.417,-23.626 160.223,-23.626 ; -7.417,-18.462 160.274,-18.462 ; -7.417,-13.297 -7.417,-28.791 94.31,-28.791 160.274,-28.791 160.274,-13.297 -7.404,-13.297 -7.404,-28.791 32.614,-28.791 ; 55.194,-28.791 55.194,-13.297 ; 87.376,-18.462 87.376,-13.297 ; 108.712,-18.462 108.712,-13.297 ; 124.511,-28.956 124.511,-23.804
  text "ALL ARTWORK VIEWED FROM TOP SIDE" at -5.804,-16.654 h1.52
  text "BOARD #:" at 57.099,-16.654 h1.52
  text ".PRJ_Number" at 70.955,-16.654 h1.52
  text "REV:" at 92.405,-16.654 h1.52
  text ".PCB_Rev" at 99.809,-16.654 h1.52
  text "SVN REV:" at 113.69,-16.654 h1.52
  text ".VersionControl_RevNumber" at 126.543,-16.654 h1.52
  text "LAYER NAME =" at -5.804,-21.806 h1.52
  text "TID #:" at 57.099,-21.819 h1.52
  text ".TID" at 70.955,-21.819 h1.52
  text "PLOT NAME =" at -5.804,-27.034 h1.52
  text ".plot_File_Name" at 14.656,-27.034 h1.52
  text "GENERATED    :" at 57.15,-27.034 h1.52
  text ".Print_Date" at 79.235,-27.034 h1.52
  text ".Print_Time" at 97.752,-27.034 h1.52
  text "TEXAS INSTRUMENTS" at 129.87,-27.034 h1.52
M12 Stackup:
  drawing of 191 lines, arcs and shapes, not listed
  text "Layer" at 249.125,196.024 h1.52
  text "Name" at 259.537,196.024 h1.52
  text "Material" at 283.152,196.024 h1.52
  text "Thickness" at 304.99,196.024 h1.52
  text "Constant" at 321.496,196.024 h1.52
  text "Board Layer Stack" at 335.971,196.024 h1.52
  text "Top Overlay" at 259.537,192.976 h1.52
  text "Top Solder" at 259.537,189.928 h1.52
  text "Solder Resist" at 283.152,189.928 h1.52
  text "0.40mil" at 304.99,189.928 h1.52
  text "3.5" at 321.496,189.928 h1.52
  text "1" at 249.125,186.88 h1.52
  text "Top Layer" at 259.537,186.88 h1.52
  text "Copper" at 283.152,186.88 h1.52
  text "1.40mil" at 304.99,186.88 h1.52
  text "Dielectric1" at 259.537,183.832 h1.52
  text "FR-4" at 283.152,183.832 h1.52
  text "59.20mil" at 304.99,183.832 h1.52
  text "4.8" at 321.496,183.832 h1.52
  text "2" at 249.125,180.784 h1.52
  text "Bottom Layer" at 259.537,180.784 h1.52
  text "Copper" at 283.152,180.784 h1.52
  text "1.40mil" at 304.99,180.784 h1.52
  text "Bottom Solder" at 259.537,177.737 h1.52
  text "Solder Resist" at 283.152,177.737 h1.52
  text "0.40mil" at 304.99,177.737 h1.52
  text "3.5" at 321.496,177.737 h1.52
  text "Bottom Overlay" at 259.537,174.689 h1.52
  text ".Layer_Name" at 14.656,-21.806 h1.52
M13 Component Bodies Top:
  text ".Layer_Name" at 14.656,-21.806 h1.52
M14 Component Bodies Bottom:
  text ".Layer_Name" at 14.656,-21.806 h1.52
M15 Courtyards Top:
  text ".Layer_Name" at 14.656,-21.806 h1.52
M16 Courtyards Bottom:
  text ".Layer_Name" at 14.656,-21.806 h1.52
Drill Drawing:
  text ".Layer_Name" at 14.656,-21.806 h1.52

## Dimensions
0,0 to 55.88,0 on M2 Board Dimensions
0,-10.16 to 25.4,-10.16 on M2 Board Dimensions
0,0 to 0,60.071 on M2 Board Dimensions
